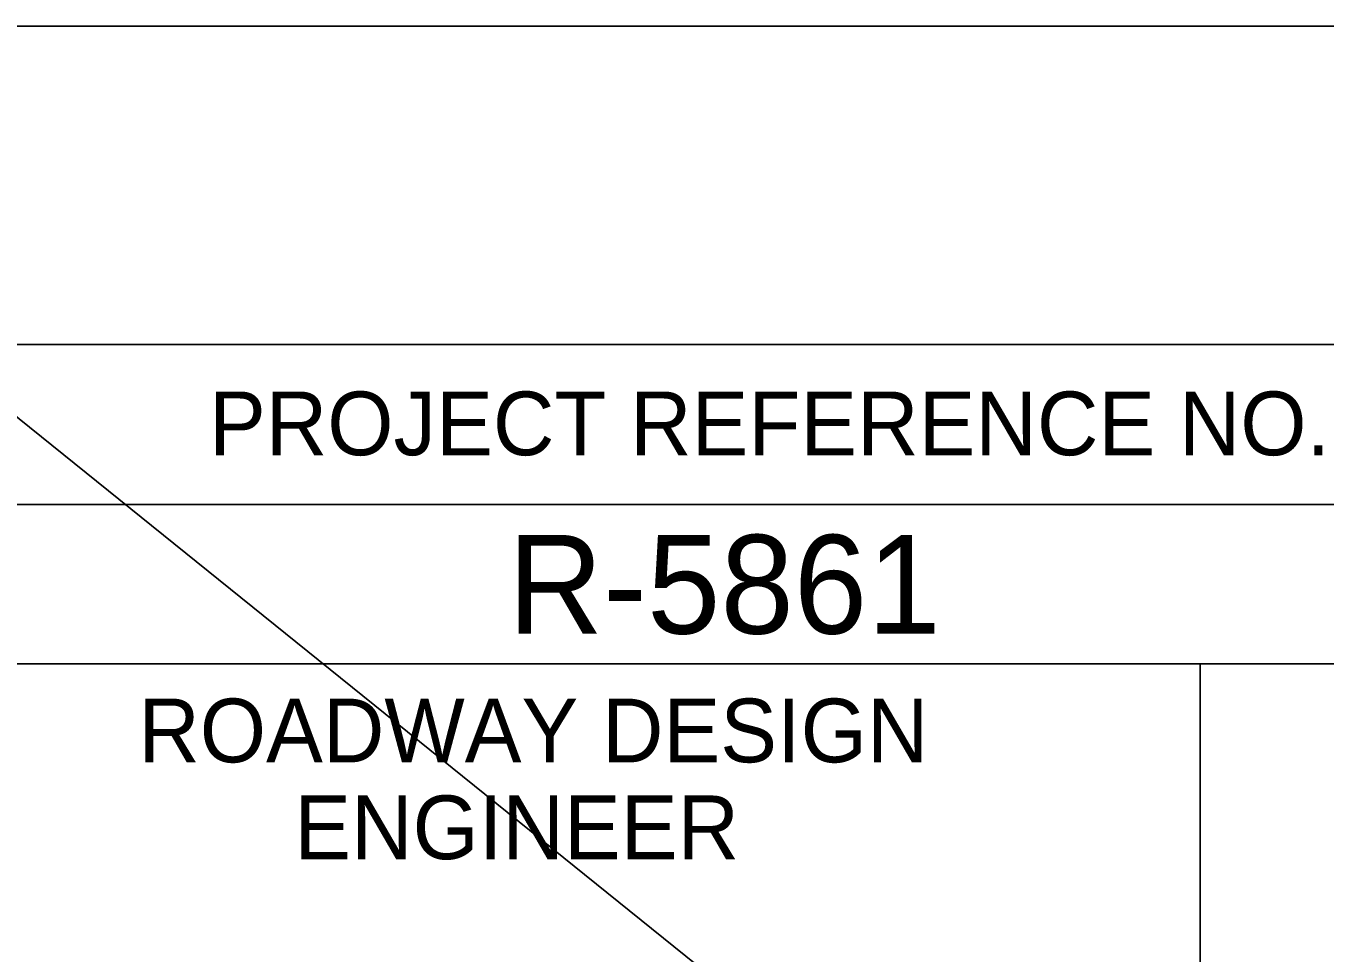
# Model space of a CAD drawing. Extents: x 505602 to 507286, y 483109 to 484209.
# Drawn here: x 507076.9 to 507178.9, y 484136 to 484208.7 of the extents above; entities that cross this region are included whole.
import ezdxf

# ---------------------------------------------------------------- set-up
doc = ezdxf.new("R2010")
doc.units = 0
for name, color, linetype in [('Sheet Data Field CELL', 7, 'Continuous'), ('Sheet Layout Profile Border Port 1', 7, 'Continuous'), ('Sheet Plot Border Outside CELL', 7, 'Continuous'), ('Sheet Profile CELL', 7, 'Continuous'), ('Sheet Profile Grid Major CELL', 7, 'Continuous')]:
    doc.layers.add(name, color=color, linetype=linetype)

msp = doc.modelspace()

# ---------------------------------------------------------------- linework, layer by layer
at = {"layer": 'Sheet Layout Profile Border Port 1'}
msp.add_lwpolyline([(505819.08, 484183.71), (505819.08, 483683.71), (507069.08, 483683.71), (507269.07, 484022.66), (507269.07, 484022.66), (507069.08, 484183.71)], close=True, dxfattribs=at)
at = {"layer": 'Sheet Plot Border Outside CELL'}
msp.add_lwpolyline([(505602.08, 483108.71), (507286.08, 483108.71), (507286.08, 484208.71), (505602.08, 484208.71)], close=True, dxfattribs=at)
at = {"layer": 'Sheet Profile CELL'}
for p, q in [((507069.03, 484171.16), (507269.08, 484171.16)), ((507169.08, 484158.66), (507169.08, 484046.21))]:
    msp.add_line(p, q, dxfattribs=at)
for points in [[(507269.08, 484183.71), (505769.08, 484183.71), (505769.08, 483133.71), (507269.08, 483133.71)], [(507069.03, 484183.71), (507269.08, 484183.71), (507269.08, 484158.66), (507069.03, 484158.66)], [(507069.03, 484158.66), (507169.08, 484158.66), (507169.08, 484046.16), (507069.03, 484046.16)], [(507169.08, 484158.66), (507269.08, 484158.66), (507269.08, 484046.16), (507169.08, 484046.16)]]:
    msp.add_lwpolyline(points, close=True, dxfattribs=at)
at = {"layer": 'Sheet Profile Grid Major CELL'}
msp.add_lwpolyline([(506869.08, 484183.71), (506919.08, 484183.71), (506919.08, 483683.71), (506969.08, 483683.71), (506969.08, 484183.71), (507019.08, 484183.71), (507019.08, 483683.71), (507069.08, 483683.71), (507069.08, 484183.71), (507095.38, 484183.71)], dxfattribs=at)

# ---------------------------------------------------------------- texts
at = {"layer": 'Sheet Data Field CELL'}
msp.add_text('R-5861', height=7.75, dxfattribs=at).set_placement((507114.7, 484161.02))
at = {"layer": 'Sheet Profile CELL'}
for s, height, p in [('PROJECT REFERENCE NO.', 5.0001, (507091.24, 484175.02)), ('ROADWAY DESIGN', 5.0001, (507085.69, 484150.92)), ('ENGINEER', 5, (507097.94, 484143.32))]:
    msp.add_text(s, height=height, dxfattribs=at).set_placement(p)

doc.saveas('drawing.dxf')
